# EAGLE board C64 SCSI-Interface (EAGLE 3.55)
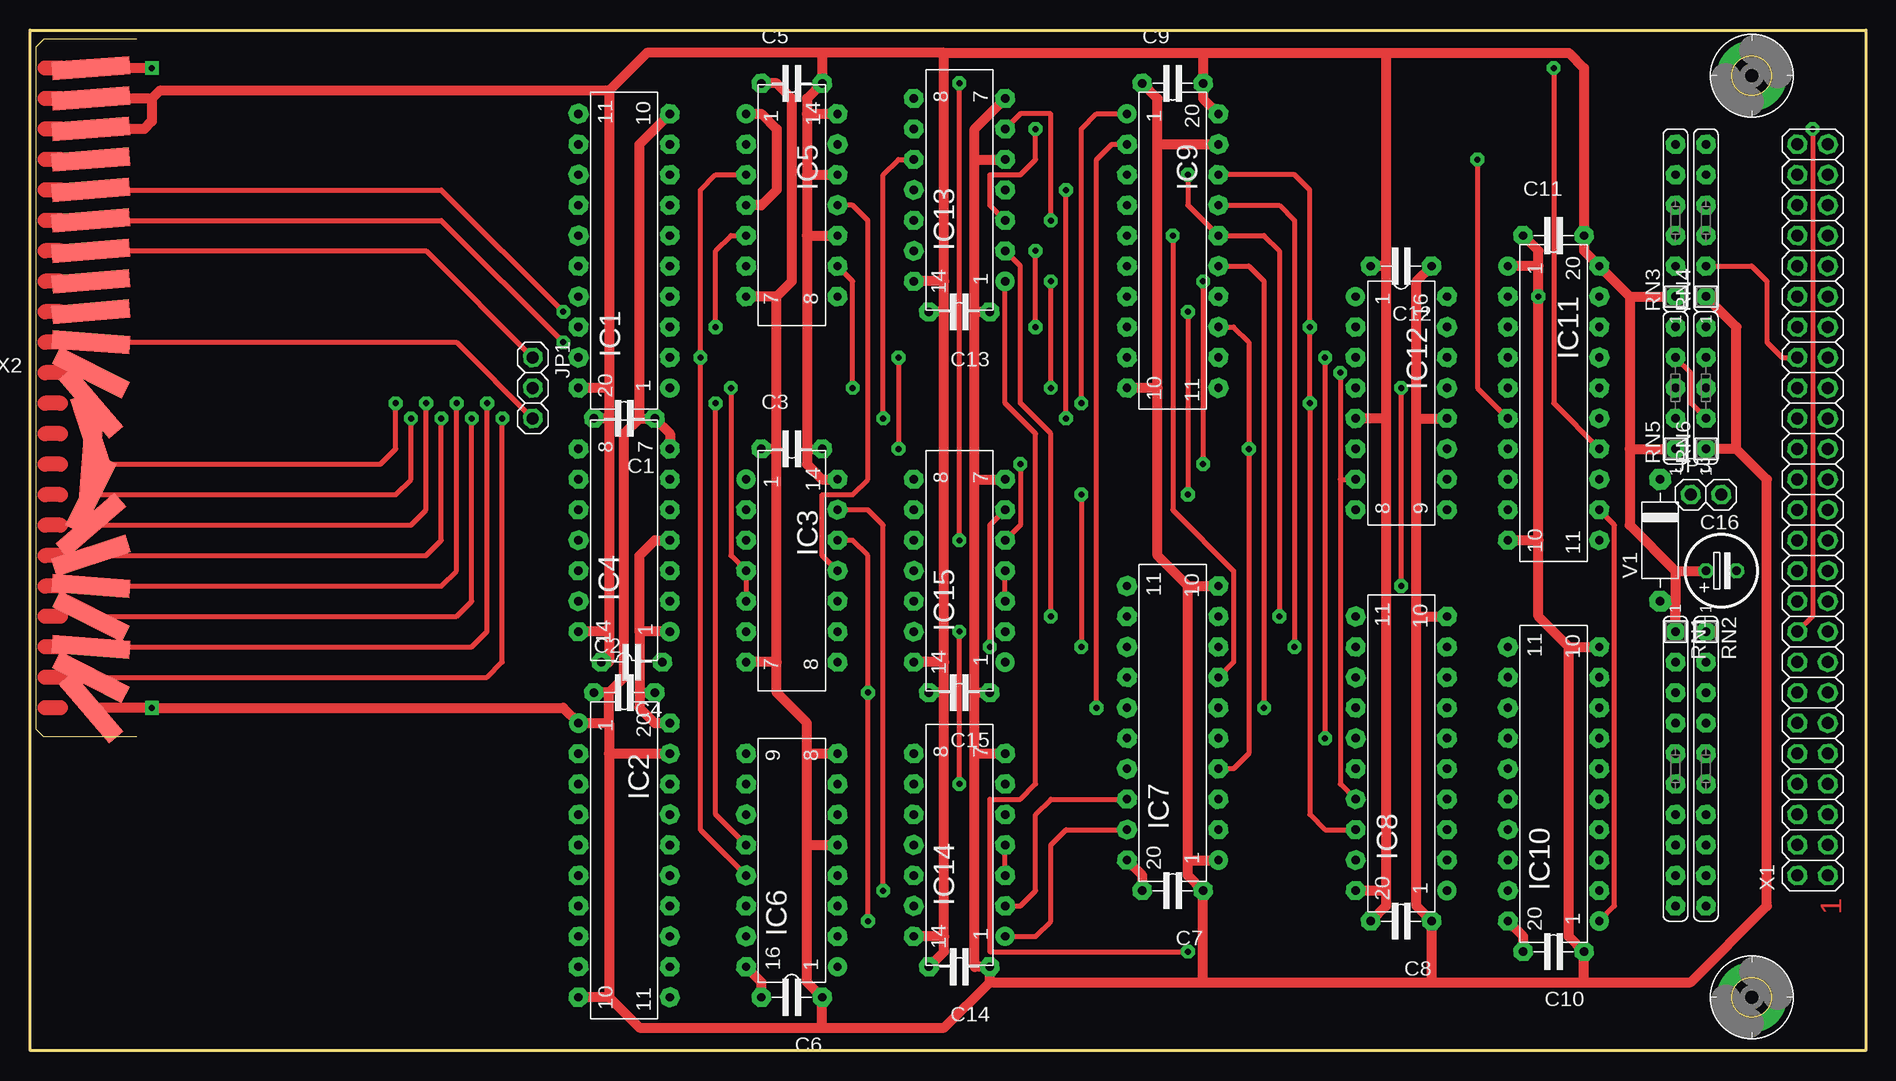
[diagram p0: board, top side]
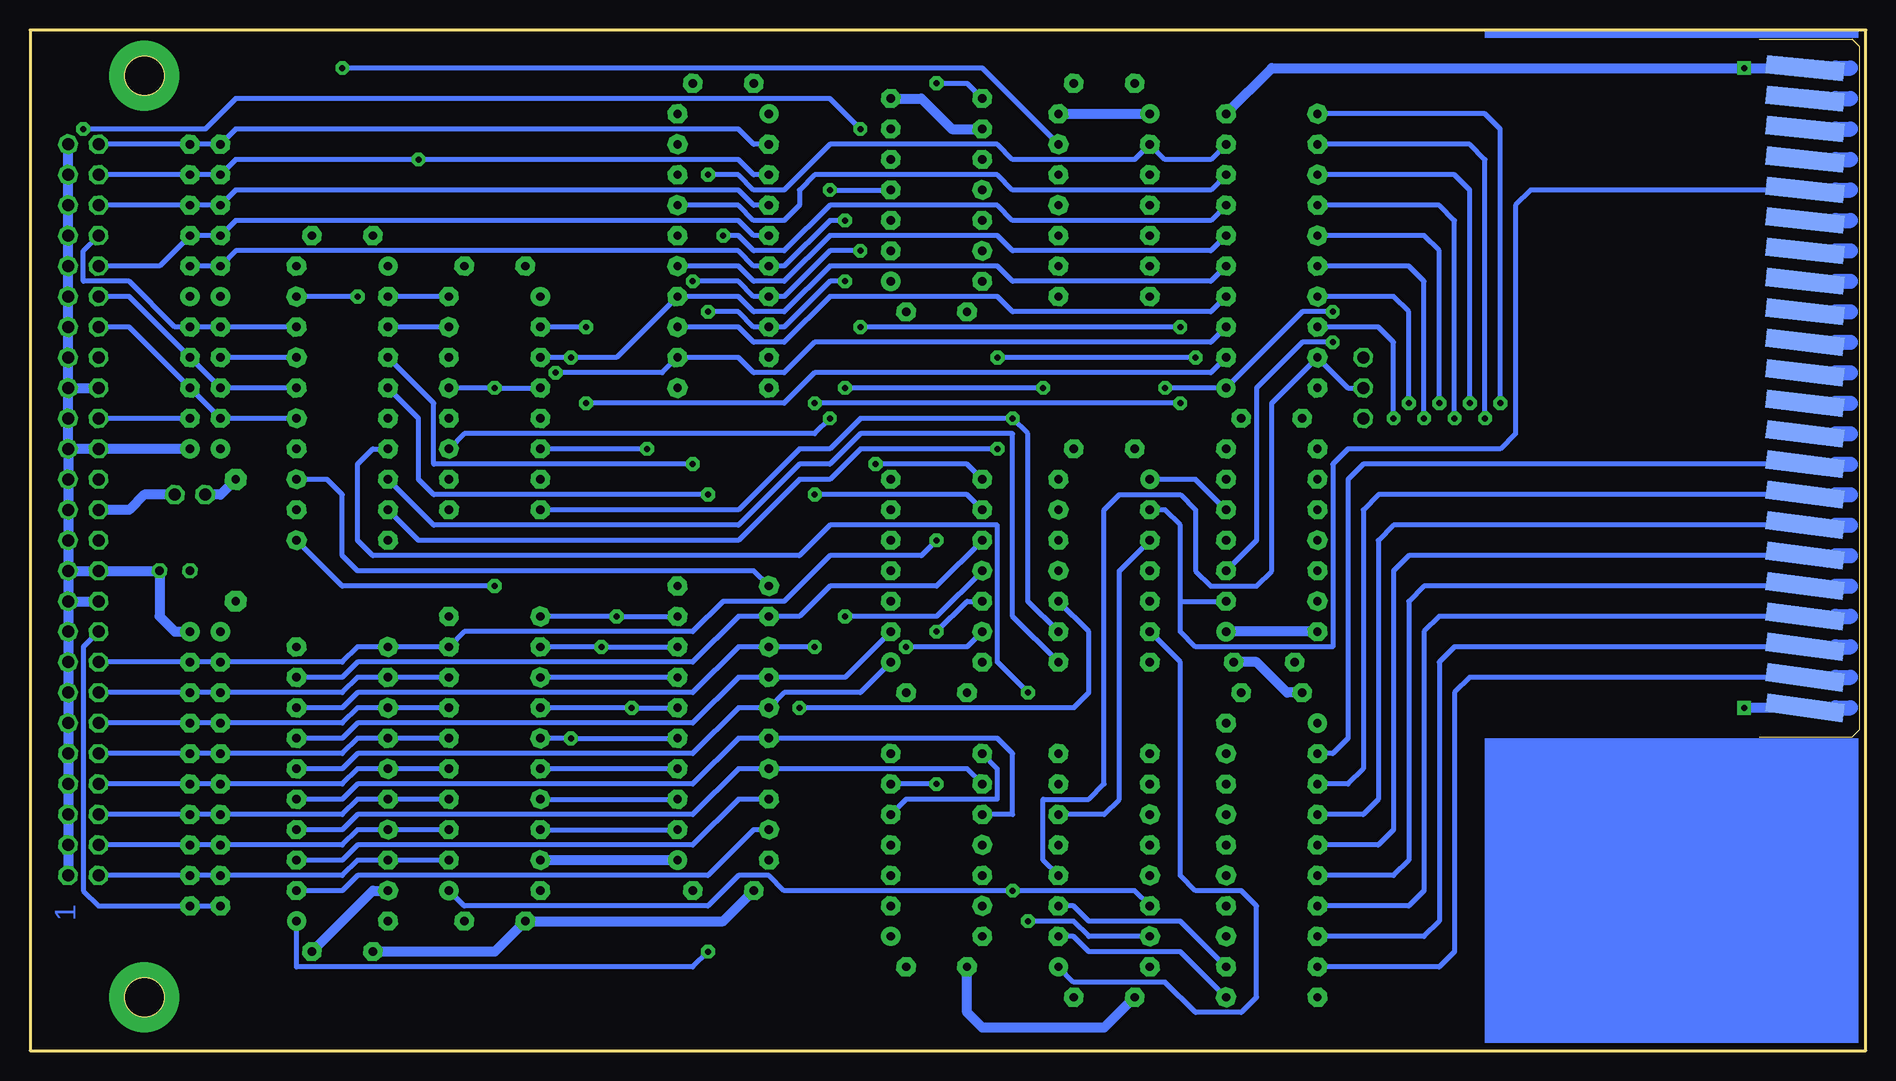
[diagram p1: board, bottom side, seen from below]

Size 153.03 x 85.09 mm. Coordinates in mm from the lower left corner, seen from the top.
Outline: 0,0 0,85.09 153.03,85.09 153.03,0 0,0
Copper layers used: Top, Bottom

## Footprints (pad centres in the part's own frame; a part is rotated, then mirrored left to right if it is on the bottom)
5 = drill 0.7 pad 1.6 octagon:  -2.54,0;  2.54,0
-2,5 = drill 0.7 pad 1.27 octagon:  -1.27,0;  1.27,0
3,2-P = drill 3.2 pad 5.842 round: 2 0,0
L20 = drill 0.7 pad 1.6 round:  -11.43,-3.81 | drill 0.7 pad 1.6 octagon:  -8.89,-3.81;  -6.35,-3.81;  -3.81,-3.81;  -1.27,-3.81;  1.27,-3.81;  3.81,-3.81;  6.35,-3.81;  8.89,-3.81;  11.43,-3.81;  11.43,3.81;  8.89,3.81;  6.35,3.81;  3.81,3.81;  1.27,3.81;  -1.27,3.81;  -3.81,3.81;  -6.35,3.81;  -8.89,3.81;  -11.43,3.81
L14 = drill 0.7 pad 1.6 round:  -7.62,-3.81 | drill 0.7 pad 1.6 octagon:  -5.08,-3.81;  -2.54,-3.81;  0,-3.81;  2.54,-3.81;  5.08,-3.81;  7.62,-3.81;  7.62,3.81;  5.08,3.81;  2.54,3.81;  0,3.81;  -2.54,3.81;  -5.08,3.81;  -7.62,3.81
L16 = drill 0.7 pad 1.6 round:  -8.89,-3.81 | drill 0.7 pad 1.6 octagon:  -6.35,-3.81;  -3.81,-3.81;  -1.27,-3.81;  1.27,-3.81;  3.81,-3.81;  6.35,-3.81;  8.89,-3.81;  8.89,3.81;  6.35,3.81;  3.81,3.81;  1.27,3.81;  -1.27,3.81;  -3.81,3.81;  -6.35,3.81;  -8.89,3.81
03 = drill 1 pad 1.6 octagon:  -2.54,0;  0,0;  2.54,0
02 = drill 1 pad 1.6 octagon:  -1.27,0;  1.27,0
L10 = drill 0.7 pad 1.6 round:  -11.43,0 | drill 0.7 pad 1.6 octagon:  -8.89,0;  -6.35,0;  -3.81,0;  -1.27,0;  1.27,0;  3.81,0;  6.35,0;  8.89,0;  11.43,0
L6 = drill 0.7 pad 1.6 round:  -6.35,0 | drill 0.7 pad 1.6 octagon:  -3.81,0;  -1.27,0;  1.27,0;  3.81,0;  6.35,0
L5 = drill 0.7 pad 1.6 round:  -5.08,0 | drill 0.7 pad 1.6 octagon:  -2.54,0;  0,0;  2.54,0;  5.08,0
10 = drill 0.7 pad 1.778 octagon:  -5.08,0;  5.08,0
25 = drill 1 pad 1.6 octagon:  -30.48,-1.27;  -30.48,1.27;  -27.94,-1.27;  -27.94,1.27;  -25.4,-1.27;  -25.4,1.27;  -22.86,-1.27;  -22.86,1.27;  -20.32,-1.27;  -20.32,1.27;  -17.78,-1.27;  -17.78,1.27;  -15.24,-1.27;  -15.24,1.27;  -12.7,-1.27;  -12.7,1.27;  -10.16,-1.27;  -10.16,1.27;  -7.62,-1.27;  -7.62,1.27;  -5.08,-1.27;  -5.08,1.27;  -2.54,-1.27;  -2.54,1.27;  0,-1.27;  0,1.27;  2.54,-1.27;  2.54,1.27;  5.08,-1.27;  5.08,1.27;  7.62,-1.27;  7.62,1.27;  10.16,-1.27;  10.16,1.27;  12.7,-1.27;  12.7,1.27;  15.24,-1.27;  15.24,1.27;  17.78,-1.27;  17.78,1.27;  20.32,1.27;  20.32,-1.27;  22.86,-1.27;  25.4,-1.27;  27.94,-1.27;  27.94,1.27;  25.4,1.27;  22.86,1.27;  30.48,1.27;  30.48,-1.27
RDCON2 = smd 1.524 x 6.477 rotated 7.9 bottom:  2.54,3.81 | smd 1.524 x 6.477 rotated 7.8 bottom:  5.08,3.81 | smd 1.524 x 6.477 rotated 7.7 bottom:  7.62,3.81 | smd 1.524 x 6.477 rotated 7.6 bottom:  10.16,3.81;  12.7,3.81 | smd 1.524 x 6.477 rotated 7.5 bottom:  15.24,3.81 | smd 1.524 x 6.477 rotated 7.4 bottom:  17.78,3.81 | smd 1.524 x 6.477 rotated 7.3 bottom:  20.32,3.81 | smd 1.524 x 6.477 rotated 7.2 bottom:  22.86,3.81 | smd 1.524 x 6.477 rotated 7 bottom:  25.4,3.81 | smd 1.524 x 6.477 rotated 6.9 bottom:  27.94,3.81 | smd 1.524 x 6.477 rotated 6.8 bottom:  30.48,3.81 | smd 1.524 x 6.477 rotated 6.7 bottom:  33.02,3.81 | smd 1.524 x 6.477 rotated 6.6 bottom:  35.56,3.81 | smd 1.524 x 6.477 rotated 6.5 bottom:  38.1,3.81 | smd 1.524 x 6.477 rotated 6.3 bottom:  40.64,3.81 | smd 1.524 x 6.477 rotated 6.2 bottom:  43.18,3.81 | smd 1.524 x 6.477 rotated 6.1 bottom:  45.72,3.81 | smd 1.524 x 6.477 rotated 6 bottom:  48.26,3.81 | smd 1.524 x 6.477 rotated 5.9 bottom:  50.8,3.81 | smd 1.524 x 6.477 rotated 5.8 bottom:  53.34,3.81 | smd 1.524 x 6.477 rotated 5.7 bottom:  55.88,3.81 | smd 1.524 x 6.477 rotated 49.4:  2.54,3.81 | smd 1.524 x 6.477 rotated 26.9:  5.08,3.81 | smd 1.524 x 6.477 rotated 4.4:  7.62,3.81;  53.34,3.81 | smd 1.524 x 6.477 rotated 206.8:  10.16,3.81 | smd 1.524 x 6.477 rotated 184.3:  12.7,3.81 | smd 1.524 x 6.477 rotated 161.8:  15.24,3.81 | smd 1.524 x 6.477 rotated 139.3:  17.78,3.81 | smd 1.524 x 6.477 rotated 116.8:  20.32,3.81 | smd 1.524 x 6.477 rotated 94.3:  22.86,3.81 | smd 1.524 x 6.477 rotated 71.8:  25.4,3.81 | smd 1.524 x 6.477 rotated 49.3:  27.94,3.81 | smd 1.524 x 6.477 rotated 26.8:  30.48,3.81 | smd 1.524 x 6.477 rotated 4.3:  33.02,3.81;  55.88,3.81 | smd 1.524 x 6.477 rotated 5:  35.56,3.81 | smd 1.524 x 6.477 rotated 4.9:  38.1,3.81 | smd 1.524 x 6.477 rotated 4.8:  40.64,3.81 | smd 1.524 x 6.477 rotated 4.7:  43.18,3.81;  45.72,3.81 | smd 1.524 x 6.477 rotated 4.6:  48.26,3.81 | smd 1.524 x 6.477 rotated 4.5:  50.8,3.81

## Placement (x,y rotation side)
C1  100n  [5]  49.53,52.7 180 top
C2  100n  [5]  49.53,29.84 0 top
C3  100n  [5]  63.5,50.16 0 top
C4  100n  [5]  50.16,32.38 180 top
C5  100n  [5]  63.5,80.65 0 top
C6  100n  [5]  63.5,4.45 180 top
C7  100n  [5]  95.25,13.34 180 top
C8  100n  [5]  114.3,10.79 180 top
C9  100n  [5]  95.25,80.65 0 top
C10  100n  [5]  127,8.26 180 top
C11  100n  [5]  127,67.95 0 top
C12  100n  [5]  114.3,65.41 180 top
C13  100n  [5]  77.47,61.59 180 top
C14  100n  [5]  77.47,6.99 180 top
C15  100n  [5]  77.47,29.84 180 top
C16  100u  [-2,5]  140.97,40 0 top
E$1  [3,2-P]  143.51,4.45 0 top
E$2  [3,2-P]  143.51,81.28 0 top
IC1  74245  [L20]  49.53,66.67 90 top
IC2  74541  [L20]  49.53,15.88 270 top
IC3  7408  [L14]  63.5,40 270 top
IC4  7474  [L14]  49.53,42.54 90 top
IC5  7474  [L14]  63.5,70.48 270 top
IC6  74138  [L16]  63.5,15.88 90 top
IC7  74573  [L20]  95.25,27.3 90 top
IC8  74540  [L20]  114.3,24.77 90 top
IC9  74540  [L20]  95.25,66.67 270 top
IC10  74540  [L20]  127,22.23 90 top
IC11  74540  [L20]  127,53.97 270 top
IC12  7475  [L16]  114.3,53.97 270 top
IC13  74125  [L14]  77.47,71.76 90 top
IC14  7486  [L14]  77.47,17.14 90 top
IC15  7486  [L14]  77.47,40 90 top
JP1  IO  [03]  41.91,55.24 270 top
JP3  TERMPWR  [02]  139.7,46.35 0 top
RN1  9*220  [L10]  137.16,23.5 270 top
RN2  9*330  [L10]  139.7,23.5 270 top
RN3  5*220  [L6]  137.16,69.22 90 top
RN4  5*330  [L6]  139.7,69.22 90 top
RN5  4*220  [L5]  137.16,55.24 90 top
RN6  4*330  [L5]  139.7,55.24 90 top
V1  1N4007  [10]  135.89,42.54 90 top
X1  scsi  [25]  148.59,45.08 90 top
X2  CARDCON22  [RDCON2]  8.89,26.04 90 top

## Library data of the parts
C1-C16 V1 = DISCRETE
E$1 E$2 = HOLES
IC1-IC15 = 74XX
JP1 JP3 X1 = PINHEAD
RN1-RN6 = R-SIL
X2 = CONNECT2

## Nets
A0: IC2. IC6.
A0-Y: IC2. X2.
A1: IC2. IC6.
A1-X: IC2. X2.
A2-W: IC2. X2.
A3-V: IC2. X2.
A4-U: IC2. X2.
A5-T: IC2. X2.
A6-S: IC2. X2.
A7-R: IC2. X2.
D0: IC1. IC7. IC8. IC9. IC12.
D0-21: IC1. X2.
D1: IC1. IC7. IC8. IC9. IC12.
D1-20: IC1. X2.
D2: IC1. IC7. IC8. IC9. IC12.
D2-19: IC1. X2.
D3: IC1. IC7. IC8. IC9. IC12.
D3-18: IC1. X2.
D4: IC1. IC7. IC8. IC9.
D4-17: IC1. X2.
D5: IC1. IC7. IC8.
D5-16: IC1. X2.
D6: IC1. IC7. IC8. IC9.
D6-15: IC1. X2.
D7: IC1. IC5. IC7. IC8. IC9.
D7-14: IC1. X2.
GND: C1. C2. C3. C4. C5. C6. C7. C8. C9. C10. C11. C12. C13. C14. C15. C16. IC1. IC2. IC3. IC4. IC5. IC6. IC7. IC8. IC9. IC10. IC11. IC12. IC13. IC14. IC15. RN2. RN4. RN6. X1. X2.
IO: IC1. IC6. JP1.
IO1-7: JP1. X2.
IO2-10: JP1. X2.
N$1: IC14.
N$2: IC3. IC4.
N$3: IC6. IC9.
N$4: IC14.
N$5: IC14. IC15.
N$6: IC15.
N$7: IC15.
N$8: IC15.
N$9: IC3. IC5.
N$10: IC7. IC10. IC14.
N$11: IC7. IC10. IC14.
N$12: IC7. IC10. IC14.
N$13: IC7. IC10. IC14.
N$14: IC7. IC10. IC15.
N$15: IC7. IC10. IC15.
N$16: IC7. IC10. IC15.
N$17: IC7. IC10. IC15.
N$18: IC13. IC15.
N$19: IC10. IC11. IC13.
N$20: IC8. IC10. IC13. RN1. RN2. X1.
N$21: IC8. IC10. RN1. RN2. X1.
N$22: IC8. IC10. RN1. RN2. X1.
N$23: IC8. IC10. RN1. RN2. X1.
N$24: IC8. IC10. RN1. RN2. X1.
N$25: IC8. IC10. RN1. RN2. X1.
N$26: IC8. IC10. RN1. RN2. X1.
N$27: IC8. IC10. RN1. RN2. X1.
N$28: IC13. RN1. RN2. X1.
N$29: IC3. IC12. IC13.
N$30: IC12. IC13.
N$31: IC9. IC13. RN3. RN4. X1.
N$32: IC9. RN3. RN4. X1.
N$33: IC9. RN3. RN4. X1.
N$34: IC9. IC11. RN3. RN4. X1.
N$35: IC3. IC9. RN3. RN4. X1.
N$36: IC5. IC9. IC11.
N$37: IC11. RN5. RN6. X1.
N$38: IC11. RN5. RN6. X1.
N$39: IC11. RN5. RN6. X1.
N$40: IC11. RN5. RN6. X1.
N$41: IC3. IC6. IC11.
N$42: IC5. IC6. IC11.
N$43: IC5. IC9. IC11.
N$44: IC3. IC6. IC8.
N$45: IC11. IC12.
N$46: IC11. IC12.
N$47: IC11. IC12.
N$49: IC5. IC11.
N$50: IC3. IC11.
N$51: IC7. IC11.
N$53: JP3. V1.
PHI2: IC3. IC6.
PHI2-E: IC3. IC4. X2.
PIXEL-6: IC4. X2.
R/-W: IC3. IC6.
R/W-5: IC1. IC3. X2.
TERMPWR: JP3. X1.
VCC: C1. C2. C3. C4. C5. C6. C7. C8. C9. C10. C11. C12. C13. C14. C15. C16. IC1. IC2. IC3. IC4. IC5. IC6. IC7. IC8. IC9. IC10. IC11. IC12. IC13. IC14. IC15. RN1. RN3. RN5. V1. X2.

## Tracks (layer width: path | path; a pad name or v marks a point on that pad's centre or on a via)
A0
  Bottom 0.406: 53.34,4.45 57.15,8.26 64.77,8.26 66.04,9.53 67.31,9.53
A0-Y
  Bottom 0.406: 45.72,6.99 35.56,6.99 34.29,8.26 34.29,29.84 33.02,31.11 5.08,31.11
A1
  Bottom 0.406: 53.34,6.99 57.15,10.79 64.77,10.79 66.04,12.07 67.31,12.07
A1-X
  Bottom 0.406: 45.72,9.53 36.83,9.53 35.56,10.79 35.56,32.38 34.29,33.65 5.08,33.65
A2-W
  Bottom 0.406: 45.72,12.07 38.1,12.07 36.83,13.34 36.83,34.92 35.56,36.2 5.08,36.2
A3-V
  Bottom 0.406: 45.72,14.61 39.37,14.61 38.1,15.88 38.1,37.46 36.83,38.73 5.08,38.73
A4-U
  Bottom 0.406: 45.72,17.14 40.64,17.14 39.37,18.41 39.37,40 38.1,41.27 5.08,41.27
A5-T
  Bottom 0.406: 45.72,19.68 41.91,19.68 40.64,20.96 40.64,42.54 39.37,43.81 5.08,43.81
A6-S
  Bottom 0.406: 45.72,22.23 43.18,22.23 41.91,23.5 41.91,45.08 40.64,46.35 5.08,46.35
A7-R
  Bottom 0.406: 45.72,24.77 44.45,24.77 43.18,26.04 43.18,47.62 41.91,48.89 5.08,48.89
D0  (via drill 0.5 pad 1.14)
  Top 0.406: 99.06,73.03 105.41,73.03 106.68,71.76 v106.68,60.32 v106.68,53.97 106.68,19.68 107.95,18.41 110.49,18.41
  Bottom 0.406: 110.49,18.41 99.06,18.41 | 53.34,57.78 54.61,56.51 87.63,56.51 90.17,53.97 v106.68,53.97 | v106.68,60.32 110.49,60.32
D0-21  (via drill 0.5 pad 1.14)
  Top 0.406: 5.08,31.11 38.1,31.11 39.37,32.38 v39.37,52.7
  Bottom 0.406: 45.72,60.32 40.64,60.32 39.37,59.05 v39.37,52.7
D1  (via drill 0.5 pad 1.14)
  Top 0.406: 109.22,47.62 109.22,22.23 110.49,20.96 | 109.22,47.62 110.49,47.62 | v109.22,56.51 109.22,47.62
  Bottom 0.406: 110.49,20.96 99.06,20.96 | 53.34,60.32 54.61,59.05 87.63,59.05 90.17,56.51 92.71,56.51 93.98,57.78 99.06,57.78 100.33,56.51 v109.22,56.51
D1-20  (via drill 0.5 pad 1.14)
  Top 0.406: 5.08,33.65 36.83,33.65 38.1,34.92 v38.1,53.97
  Bottom 0.406: 45.72,62.87 39.37,62.87 38.1,61.59 v38.1,53.97
D2  (via drill 0.5 pad 1.14)
  Top 0.406: 99.06,60.32 100.33,60.32 101.6,59.05 v101.6,50.16 101.6,24.77 100.33,23.5 99.06,23.5
  Bottom 0.406: 99.06,23.5 110.49,23.5 | 53.34,62.87 54.61,61.59 71.12,61.59 72.39,62.87 86.36,62.87 90.17,59.05 92.71,59.05 93.98,60.32 99.06,60.32 | v101.6,50.16 110.49,50.16
D2-19  (via drill 0.5 pad 1.14)
  Top 0.406: 5.08,36.2 35.56,36.2 36.83,37.46 v36.83,52.7
  Bottom 0.406: 45.72,65.41 38.1,65.41 36.83,64.14 v36.83,52.7
D3  (via drill 0.5 pad 1.14)
  Top 0.406: v107.95,57.78 v107.95,26.04
  Bottom 0.406: 99.06,26.04 v107.95,26.04 110.49,26.04 | 53.34,65.41 54.61,64.14 71.12,64.14 72.39,65.41 86.36,65.41 90.17,61.59 92.71,61.59 93.98,62.87 99.06,62.87 104.14,57.78 v107.95,57.78 110.49,57.78
D3-18  (via drill 0.5 pad 1.14)
  Top 0.406: 5.08,38.73 34.29,38.73 35.56,40 v35.56,53.97
  Bottom 0.406: 45.72,67.95 36.83,67.95 35.56,66.67 v35.56,53.97
D4  (via drill 0.5 pad 1.14)
  Top 0.406: 99.06,65.41 101.6,65.41 102.87,64.14 v102.87,28.57
  Bottom 0.406: 99.06,28.57 v102.87,28.57 110.49,28.57 | 53.34,67.95 54.61,66.67 71.12,66.67 72.39,67.95 86.36,67.95 90.17,64.14 92.71,64.14 93.98,65.41 99.06,65.41
D4-17  (via drill 0.5 pad 1.14)
  Top 0.406: 5.08,41.27 33.02,41.27 34.29,42.54 v34.29,52.7
  Bottom 0.406: 45.72,70.48 35.56,70.48 34.29,69.22 v34.29,52.7
D5  (via drill 0.5 pad 1.14)
  Top 0.406: 99.06,31.11 100.33,32.38 100.33,40 95.25,45.08 v95.25,67.95
  Bottom 0.406: 99.06,31.11 110.49,31.11 | 53.34,70.48 54.61,69.22 71.12,69.22 72.39,70.48 86.36,70.48 90.17,66.67 92.71,66.67 93.98,67.95 v95.25,67.95
D5-16  (via drill 0.5 pad 1.14)
  Top 0.406: 5.08,43.81 31.75,43.81 33.02,45.08 v33.02,53.97
  Bottom 0.406: 45.72,73.03 34.29,73.03 33.02,71.76 v33.02,53.97
D6  (via drill 0.5 pad 1.14)
  Top 0.406: 99.06,70.48 104.14,70.48 105.41,69.22 v105.41,33.65
  Bottom 0.406: 99.06,33.65 v105.41,33.65 110.49,33.65 | 53.34,73.03 54.61,71.76 71.12,71.76 72.39,73.03 87.63,73.03 88.9,71.76 88.9,70.48 90.17,69.22 92.71,69.22 93.98,70.48 99.06,70.48
D6-15  (via drill 0.5 pad 1.14)
  Top 0.406: 5.08,46.35 30.48,46.35 31.75,47.62 v31.75,52.7
  Bottom 0.406: 45.72,75.56 33.02,75.56 31.75,74.3 v31.75,52.7
D7  (via drill 0.5 pad 1.14)
  Top 0.406: v104.14,36.2 104.14,66.67 102.87,67.95 99.06,67.95 96.52,70.48 v96.52,73.03
  Bottom 0.406: 99.06,36.2 v104.14,36.2 110.49,36.2 | v96.52,73.03 93.98,73.03 92.71,71.76 90.17,71.76 86.36,75.56 72.39,75.56 71.12,74.3 60.96,74.3 59.69,75.56 58.42,74.3 54.61,74.3 53.34,75.56
D7-14  (via drill 0.5 pad 1.14)
  Top 0.406: 5.08,48.89 29.21,48.89 30.48,50.16 v30.48,53.97
  Bottom 0.406: 45.72,78.11 31.75,78.11 30.48,76.84 v30.48,53.97
GND  (via drill 0.5 pad 1.14)
  Top 0.813: 124.46,67.95 125.73,66.67 125.73,65.41 | 125.73,65.41 123.19,65.41 | 125.73,42.54 v125.73,62.87 125.73,65.41 | 125.73,42.54 123.19,42.54 | 92.71,80.65 93.98,79.38 93.98,75.56 | 93.98,55.24 93.98,75.56 | 93.98,55.24 91.44,55.24 | 78.74,61.59 80.01,61.59 | 78.74,61.59 78.74,74.3 | 78.74,74.3 81.28,74.3 | 78.74,74.3 78.74,76.84 81.28,79.38 | 116.84,65.41 115.57,64.14 115.57,52.7 | 115.57,52.7 118.11,52.7 | 96.52,15.88 96.52,14.61 97.79,13.34 97.79,5.71 | 96.52,15.88 99.06,15.88 | 96.52,15.88 96.52,38.73 | 96.52,38.73 99.06,38.73 | 115.57,36.2 118.11,36.2 | 115.57,36.2 115.57,12.07 116.84,10.79 116.84,5.71 | 128.27,33.65 130.81,33.65 | 128.27,33.65 128.27,9.53 129.54,8.26 129.54,5.71 | 78.74,24.77 81.28,24.77 | 78.74,24.77 78.74,6.99 80.01,6.99 80.01,5.71 | 50.8,52.7 50.8,75.56 53.34,78.11 | 50.8,52.7 52.07,52.7 53.34,51.43 53.34,50.16 | 62.23,32.38 59.69,32.38 | 62.23,32.38 62.23,50.16 | 62.23,50.16 60.96,50.16 | 60.96,80.65 62.23,80.65 63.5,79.38 63.5,64.14 62.23,62.87 | 62.23,62.87 59.69,62.87 | 48.26,29.84 46.99,29.84 | 48.26,27.3 48.26,29.84 | 48.26,27.3 45.72,27.3 44.45,28.57 v10.16,28.57 5.08,28.57 | 78.74,29.84 80.01,29.84 | 78.74,24.77 78.74,29.84 | 78.74,47.62 81.28,47.62 | 78.74,29.84 78.74,47.62 | 78.74,47.62 78.74,61.59 | 64.77,17.14 64.77,5.71 66.04,4.45 66.04,1.9 | 64.77,17.14 64.77,24.77 | 64.77,24.77 67.31,24.77 | 139.7,62.87 142.24,60.32 142.24,50.16 | 142.24,50.16 139.7,50.16 | 115.57,36.2 115.57,52.7 | 125.73,42.54 125.73,36.2 128.27,33.65 | 93.98,55.24 93.98,41.27 96.52,38.73 | 66.04,1.9 76.2,1.9 80.01,5.71 | 80.01,5.71 97.79,5.71 | 97.79,5.71 116.84,5.71 | 116.84,5.71 129.54,5.71 | 62.23,32.38 62.23,29.84 64.77,27.3 64.77,24.77
  Top 0.813: 62.23,50.16 62.23,62.87 | 50.8,52.7 49.53,51.43 49.53,31.11 48.26,29.84 | 48.26,27.3 48.26,24.77 | 48.26,24.77 48.26,4.45 | 48.26,4.45 45.72,4.45 | 48.26,4.45 50.8,1.9 66.04,1.9 | 48.26,24.77 53.34,24.77 | 64.77,17.14 67.31,17.14 | 93.98,75.56 99.06,75.56 | 142.24,50.16 144.78,47.62 144.78,12.07 138.43,5.71 129.54,5.71 | v10.16,81.92 X2.
  Bottom 0.406: v125.73,62.87 130.81,62.87
  Bottom 0.813: X1. 149.86,73.03 149.86,70.48 149.86,67.95 149.86,65.41 149.86,62.87 149.86,60.32 149.86,57.78 149.86,55.24 | 149.86,55.24 149.86,52.7 149.86,50.16 | 149.86,50.16 149.86,47.62 149.86,45.08 149.86,42.54 149.86,40 | 149.86,40 149.86,37.46 | 149.86,37.46 149.86,34.92 149.86,32.38 149.86,29.84 149.86,27.3 149.86,24.77 149.86,22.23 149.86,19.68 149.86,17.14 149.86,14.61 | 149.86,55.24 147.32,55.24 | 149.86,50.16 147.32,50.16 139.7,50.16 | 149.86,37.46 147.32,37.46 | 149.86,40 147.32,40 C16. 142.24,36.2 140.97,34.92 139.7,34.92 | 99.06,15.88 110.49,15.88 | 73.66,76.84 76.2,76.84 78.74,79.38 81.28,79.38 | 123.19,13.34 124.46,13.34 129.54,8.26 | 52.7,32.38 50.8,32.38 48.26,29.84 46.99,29.84 | 53.34,78.11 49.53,81.92 v10.16,81.92 X2. | 5.08,28.57 v10.16,28.57
IO
  Bottom 0.406: 41.91,55.24 43.18,55.24 45.72,57.78 49.53,53.97 49.53,40 50.8,38.73 54.61,38.73 55.88,40 55.88,45.08 57.15,46.35 62.23,46.35 63.5,45.08 63.5,22.23 64.77,20.96 68.58,20.96 68.58,15.88 67.31,14.61
IO1-7
  Top 0.406: 5.08,66.67 33.02,66.67 41.91,57.78
IO2-10
  Top 0.406: 5.08,59.05 35.56,59.05 JP1.
N$1
  Top 0.406: 81.28,14.61 81.28,17.14
N$2
  Bottom 0.406: 59.69,47.62 55.88,47.62 53.34,45.08
N$3  (via drill 0.5 pad 1.14)
  Top 0.406: 59.69,17.14 57.15,19.68 v57.15,53.97 | v87.63,53.97 87.63,76.84 88.9,78.11 91.44,78.11
  Bottom 0.406: v57.15,53.97 v87.63,53.97
N$4
  Bottom 0.406: 81.28,19.68 80.01,20.96 72.39,20.96 72.39,23.5 73.66,24.77
N$5  (via drill 0.5 pad 1.14)
  Top 0.406: v77.47,22.23 v77.47,34.92
  Bottom 0.406: 73.66,37.46 74.93,37.46 v77.47,34.92 | v77.47,22.23 81.28,22.23
N$6  (via drill 0.5 pad 1.14)
  Top 0.406: 81.28,45.08 80.01,43.81 v80.01,33.65
  Bottom 0.406: v80.01,33.65 74.93,33.65 73.66,34.92
N$7
  Top 0.406: 81.28,37.46 81.28,40
N$8  (via drill 0.5 pad 1.14)
  Top 0.406: v82.55,48.89 82.55,43.81 81.28,42.54
  Bottom 0.406: 73.66,47.62 74.93,48.89 v82.55,48.89
N$9
  Top 0.406: 67.31,70.48 68.58,70.48 69.85,69.22 69.85,47.62 68.58,46.35 66.04,46.35 66.04,41.27 67.31,40
N$10
  Top 0.406: 91.44,18.41 86.36,18.41 85.09,17.14 85.09,10.79 83.82,9.53 81.28,9.53
  Bottom 0.406: 130.81,13.34 127,13.34 125.73,14.61 96.52,14.61 92.71,18.41 91.44,18.41
N$11
  Top 0.406: 91.44,20.96 85.09,20.96 83.82,19.68 83.82,13.34 82.55,12.07 81.28,12.07
  Bottom 0.406: 130.81,15.88 127,15.88 125.73,17.14 97.79,17.14 93.98,20.96 91.44,20.96
N$12
  Bottom 0.406: 130.81,18.41 127,18.41 125.73,19.68 97.79,19.68 93.98,23.5 91.44,23.5 74.93,23.5 73.66,22.23
N$13
  Bottom 0.406: 130.81,20.96 127,20.96 125.73,22.23 97.79,22.23 93.98,26.04 91.44,26.04 72.39,26.04 71.12,24.77 71.12,19.68 73.66,19.68
N$14
  Bottom 0.406: 130.81,23.5 127,23.5 125.73,24.77 97.79,24.77 93.98,28.57 91.44,28.57 90.17,29.84 83.82,29.84 81.28,32.38
N$15
  Bottom 0.406: 130.81,26.04 127,26.04 125.73,27.3 97.79,27.3 93.98,31.11 91.44,31.11 85.09,31.11 81.28,34.92
N$16  (via drill 0.5 pad 1.14)
  Top 0.406: v87.63,46.35 v87.63,33.65
  Bottom 0.406: 130.81,28.57 127,28.57 125.73,29.84 97.79,29.84 93.98,33.65 91.44,33.65 v87.63,33.65 | 73.66,45.08 74.93,46.35 v87.63,46.35
N$17
  Bottom 0.406: 130.81,31.11 127,31.11 125.73,32.38 97.79,32.38 93.98,36.2 91.44,36.2 88.9,36.2 86.36,38.73 77.47,38.73 73.66,42.54
N$18  (via drill 0.5 pad 1.14)
  Top 0.406: 81.28,66.67 82.55,65.41 82.55,53.97 85.09,51.43 v85.09,36.2
  Bottom 0.406: 73.66,40 77.47,36.2 v85.09,36.2
N$19  (via drill 0.5 pad 1.14)
  Top 0.406: 130.81,45.08 132.08,43.81 132.08,12.07 130.81,10.79 | 81.28,64.14 81.28,53.97 83.82,51.43 83.82,22.23 82.55,20.96 80.01,20.96 80.01,8.26 v96.52,8.26
  Bottom 0.406: v96.52,8.26 97.79,6.99 130.81,6.99 130.81,10.79
N$20  (via drill 0.5 pad 1.14)
  Top 0.406: v77.47,42.54 v77.47,80.65
  Bottom 0.406: 147.32,32.38 139.7,32.38 137.16,32.38 127,32.38 125.73,33.65 123.19,33.65 118.11,33.65 116.84,34.92 97.79,34.92 95.25,37.46 90.17,37.46 86.36,41.27 78.74,41.27 v77.47,42.54 | 73.66,79.38 74.93,80.65 v77.47,80.65
N$21
  Bottom 0.406: 147.32,29.84 139.7,29.84 137.16,29.84 127,29.84 125.73,31.11 123.19,31.11 118.11,31.11
N$22
  Bottom 0.406: 147.32,27.3 139.7,27.3 137.16,27.3 127,27.3 125.73,28.57 123.19,28.57 118.11,28.57
N$23
  Bottom 0.406: 147.32,24.77 139.7,24.77 137.16,24.77 127,24.77 125.73,26.04 123.19,26.04 118.11,26.04
N$24
  Bottom 0.406: 147.32,22.23 139.7,22.23 137.16,22.23 127,22.23 125.73,23.5 123.19,23.5 118.11,23.5
N$25
  Bottom 0.406: 147.32,19.68 139.7,19.68 137.16,19.68 127,19.68 125.73,20.96 123.19,20.96 118.11,20.96
N$26
  Bottom 0.406: 147.32,17.14 139.7,17.14 137.16,17.14 127,17.14 125.73,18.41 123.19,18.41 118.11,18.41
N$27
  Bottom 0.406: 147.32,14.61 139.7,14.61 137.16,14.61 127,14.61 125.73,15.88 123.19,15.88 118.11,15.88
N$28  (via drill 0.5 pad 1.14)
  Top 0.406: 147.32,34.92 148.59,36.2 v148.59,76.84 | v83.82,76.84 83.82,74.3 82.55,73.03 80.01,73.03 80.01,70.48 81.28,69.22
  Bottom 0.406: RN1. RN2. 147.32,12.07 148.59,13.34 148.59,33.65 147.32,34.92 | v148.59,76.84 138.43,76.84 135.89,79.38 86.36,79.38 v83.82,76.84
N$29  (via drill 0.5 pad 1.14)
  Top 0.406: 73.66,74.3 72.39,74.3 71.12,73.03 v71.12,52.7
  Bottom 0.406: 67.31,34.92 69.85,37.46 69.85,51.43 v71.12,52.7 83.82,52.7 86.36,50.16 88.9,50.16 93.98,45.08 110.49,45.08
N$30  (via drill 0.5 pad 1.14)
  Top 0.406: v86.36,52.7 v86.36,71.76
  Bottom 0.406: 118.11,50.16 116.84,51.43 87.63,51.43 v86.36,52.7 | v86.36,71.76 81.28,71.76
N$31  (via drill 0.5 pad 1.14)
  Top 0.406: 147.32,57.78 146.05,57.78 144.78,59.05 144.78,64.14 143.51,65.41 139.7,65.41 | 81.28,76.84 82.55,78.11 85.09,78.11 v85.09,69.22
  Bottom 0.406: 139.7,65.41 137.16,65.41 135.89,66.67 93.98,66.67 92.71,65.41 91.44,65.41 90.17,65.41 86.36,69.22 v85.09,69.22
N$32
  Bottom 0.406: 147.32,65.41 142.24,65.41 139.7,67.95 137.16,67.95 135.89,69.22 93.98,69.22 92.71,67.95 91.44,67.95
N$33
  Bottom 0.406: 147.32,70.48 139.7,70.48 137.16,70.48 135.89,71.76 93.98,71.76 92.71,70.48 91.44,70.48
N$34  (via drill 0.5 pad 1.14)
  Top 0.406: 123.19,52.7 120.65,55.24 v120.65,74.3
  Bottom 0.406: 147.32,73.03 139.7,73.03 137.16,73.03 135.89,74.3 v120.65,74.3 93.98,74.3 92.71,73.03 91.44,73.03
N$35  (via drill 0.5 pad 1.14)
  Top 0.406: 91.44,75.56 90.17,75.56 88.9,74.3 v88.9,28.57
  Bottom 0.406: 147.32,75.56 RN4. RN3. 135.89,76.84 93.98,76.84 92.71,75.56 91.44,75.56 | 67.31,37.46 64.77,34.92 64.77,29.84 66.04,28.57 v88.9,28.57
N$36  (via drill 0.5 pad 1.14)
  Top 0.406: v96.52,61.59 v96.52,46.35 | 67.31,65.41 68.58,64.14 v68.58,55.24 | v85.09,55.24 v85.09,64.14
  Bottom 0.406: 123.19,55.24 120.65,52.7 120.65,47.62 119.38,46.35 v96.52,46.35 | v96.52,61.59 93.98,61.59 92.71,60.32 91.44,60.32 90.17,60.32 86.36,64.14 v85.09,64.14 | v68.58,55.24 v85.09,55.24
N$37
  Bottom 0.406: 130.81,52.7 137.16,52.7 139.7,55.24 144.78,60.32 147.32,60.32
N$38
  Bottom 0.406: 130.81,55.24 137.16,55.24 139.7,57.78 144.78,62.87 147.32,62.87
N$39
  Top 0.406: 137.16,57.78 138.43,56.51 138.43,53.97 139.7,52.7
  Bottom 0.406: 130.81,57.78 137.16,57.78 | 139.7,52.7 147.32,52.7
N$40
  Bottom 0.406: 130.81,60.32 RN5. RN6. 140.97,60.32 144.78,64.14 148.59,64.14 148.59,66.67 147.32,67.95
N$41  (via drill 0.5 pad 1.14)
  Top 0.406: 67.31,42.54 68.58,42.54 69.85,41.27 v69.85,29.84 v69.85,10.79
  Bottom 0.406: 59.69,9.53 64.77,9.53 66.04,10.79 v69.85,10.79 | 123.19,50.16 124.46,50.16 125.73,48.89 125.73,42.54 124.46,41.27 88.9,41.27 86.36,43.81 72.39,43.81 72.39,32.38 v69.85,29.84
N$42  (via drill 0.5 pad 1.14)
  Top 0.406: 59.69,14.61 55.88,18.41 v55.88,57.78 55.88,71.76 57.15,73.03 59.69,73.03 | v72.39,57.78 v72.39,50.16
  Bottom 0.406: 123.19,45.08 120.65,42.54 93.98,42.54 88.9,47.62 86.36,47.62 83.82,50.16 v72.39,50.16 | v55.88,57.78 v72.39,57.78
N$43  (via drill 0.5 pad 1.14)
  Top 0.406: v97.79,64.14 v97.79,48.89 | 59.69,67.95 58.42,67.95 57.15,66.67 v57.15,60.32 | v83.82,60.32 v83.82,66.67
  Bottom 0.406: 123.19,57.78 119.38,53.97 119.38,48.89 v97.79,48.89 | v97.79,64.14 93.98,64.14 92.71,62.87 91.44,62.87 90.17,62.87 86.36,66.67 v83.82,66.67 | v57.15,60.32 v83.82,60.32
N$44  (via drill 0.5 pad 1.14)
  Top 0.406: 67.31,45.08 69.85,45.08 71.12,43.81 v71.12,13.34
  Bottom 0.406: 118.11,13.34 116.84,12.07 96.52,12.07 93.98,14.61 91.44,14.61 90.17,13.34 v71.12,13.34 60.96,13.34 59.69,12.07
N$45  (via drill 0.5 pad 1.14)
  Top 0.406: v114.3,38.73 v114.3,55.24
  Bottom 0.406: 110.49,55.24 v114.3,55.24 118.11,55.24 | 130.81,42.54 127,38.73 v114.3,38.73
N$46
  Bottom 0.406: IC12. 123.19,62.87
N$47
  Bottom 0.406: 118.11,60.32 123.19,60.32
N$49  (via drill 0.5 pad 1.14)
  Top 0.406: v127,81.92 127,53.97 130.81,50.16
  Bottom 0.406: 67.31,75.56 73.66,81.92 v127,81.92
N$50
  Bottom 0.406: 67.31,32.38 71.12,36.2 71.12,51.43 83.82,51.43 86.36,48.89 88.9,48.89 93.98,43.81 119.38,43.81 123.19,47.62
N$51
  Bottom 0.406: 91.44,38.73 92.71,40 125.73,40 127,41.27 127,46.35 128.27,47.62 130.81,47.62
N$53
  Bottom 0.813: V1. 137.16,46.35 138.43,46.35
PHI2
  Bottom 0.406: 59.69,42.54 62.23,40 62.23,20.96 63.5,19.68 67.31,19.68
PHI2-E
  Bottom 0.406: 57.15,37.46 57.15,34.92 55.88,33.65 44.45,33.65 44.45,48.89 43.18,50.16 30.48,50.16 29.21,51.43 29.21,70.48 27.94,71.76 5.08,71.76 | 57.15,37.46 53.34,37.46 | 59.69,45.08 58.42,45.08 57.15,43.81 57.15,37.46
PIXEL-6  (via drill 0.5 pad 1.14)
  Top 0.406: v44.45,59.05 34.29,69.22 5.08,69.22
  Bottom 0.406: 53.34,40 50.8,42.54 50.8,55.24 46.99,59.05 v44.45,59.05
R/-W
  Bottom 0.406: 59.69,34.92 57.15,32.38 57.15,14.61 55.88,13.34 52.07,13.34 50.8,12.07 50.8,4.45 52.07,3.18 55.88,3.18 58.42,5.71 66.04,5.71 67.31,6.99
R/W-5  (via drill 0.5 pad 1.14)
  Top 0.406: 59.69,37.46 59.69,40 58.42,41.27 v58.42,55.24 | 5.08,71.76 34.29,71.76 v44.45,61.59
  Bottom 0.406: v58.42,55.24 53.34,55.24 46.99,61.59 v44.45,61.59
TERMPWR
  Bottom 0.813: 147.32,45.08 144.78,45.08 143.51,46.35 JP3.
VCC
  Top 0.813: 135.89,37.46 137.16,37.46 137.16,34.92 137.16,40 | IC9. 97.79,79.38 C9. 97.79,83.19 | 113.03,65.41 C12. | 113.03,65.41 113.03,52.7 | 113.03,52.7 110.49,52.7 | 76.2,61.59 C13. | 76.2,61.59 76.2,64.14 | 76.2,64.14 IC13. | C7. 92.71,14.61 IC7. | 113.03,13.34 113.03,12.07 C8. | 113.03,13.34 IC8. | C10. 124.46,9.53 IC10. | 76.2,9.53 IC14. | 76.2,9.53 76.2,8.26 C14. | 76.2,29.84 C15. | 76.2,29.84 76.2,32.38 | 76.2,32.38 IC15. | 76.2,9.53 76.2,29.84 | 48.26,55.24 IC1. | 48.26,55.24 48.26,52.7 | 48.26,52.7 C1. | 48.26,34.92 IC4. | 48.26,34.92 48.26,32.38 C4. | 48.26,52.7 48.26,34.92 | 64.77,50.16 C3. | 64.77,50.16 64.77,48.89 66.04,47.62 IC3. | 64.77,78.11 64.77,79.38 C5. 66.04,83.19 | 64.77,78.11 IC5. | 64.77,67.95 64.77,50.16 | 64.77,73.03 64.77,67.95 | 64.77,78.11 64.77,73.03 | 76.2,32.38 76.2,61.59 | 113.03,52.7 113.03,13.34 | 50.8,29.84 C2. | 50.8,29.84 50.8,28.57 52.07,27.3 IC2. | 50.8,34.92 50.8,29.84 | 53.34,34.92 50.8,34.92 | 50.8,34.92 50.8,41.27 52.07,42.54 53.34,42.54 | 64.77,73.03 67.31,73.03 | 64.77,67.95 67.31,67.95 | IC6. 60.96,5.71 C6. | 133.35,62.87 137.16,62.87 | 133.35,62.87 133.35,50.16 | 133.35,62.87 IC11. 129.54,66.67 C11. 129.54,81.92 128.27,83.19 113.03,83.19 | 133.35,50.16 137.16,50.16 | 133.35,50.16 133.35,43.81 137.16,40 | 137.16,40 139.7,40 | 48.26,80.01 48.26,55.24 | 66.04,83.19 51.43,83.19 48.26,80.01 | 76.2,83.19 66.04,83.19 | 76.2,83.19 97.79,83.19 | 97.79,83.19 113.03,83.19 | 113.03,83.19 113.03,65.41 | 76.2,64.14 76.2,83.19 | 59.69,78.11 60.96,78.11 62.23,76.84 62.23,71.76 60.96,70.48 59.69,70.48 | 10.16,79.38 10.16,77.47 9.53,76.84 5.08,76.84 | 48.26,80.01 10.79,80.01 10.16,79.38 | 10.16,79.38 5.08,79.38
  Bottom 0.813: C7. 95.25,10.79 C8. 114.3,8.26 C10. | C6. 63.5,1.9 73.66,1.9 74.93,3.18 C14. | IC4. 53.34,34.92 | IC5. 59.69,78.11
(copper drawn outside any net)
  shapes: Bottom area x2

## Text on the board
Top: 1
Bottom: 1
